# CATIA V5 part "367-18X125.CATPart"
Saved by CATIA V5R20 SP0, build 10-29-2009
Part number: 367-18X125
Definition: NONE
Nomenclature: 367-18X125
Source: Unknown
Description: 367-18X125
Bounding box of the stored display mesh (mm): x 0 to 125, y -14 to 14, z -14 to 14
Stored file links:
  C:\Users\Utente\Desktop\IO LAVORO\3D X SITO CF\X SITO\PLASTICA\3D files 367\367-18X125.CATPart
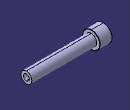
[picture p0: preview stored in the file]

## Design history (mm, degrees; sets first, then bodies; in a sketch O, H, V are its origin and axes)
Body1 "367-18X125" (main body)
  Solid1: solid without history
